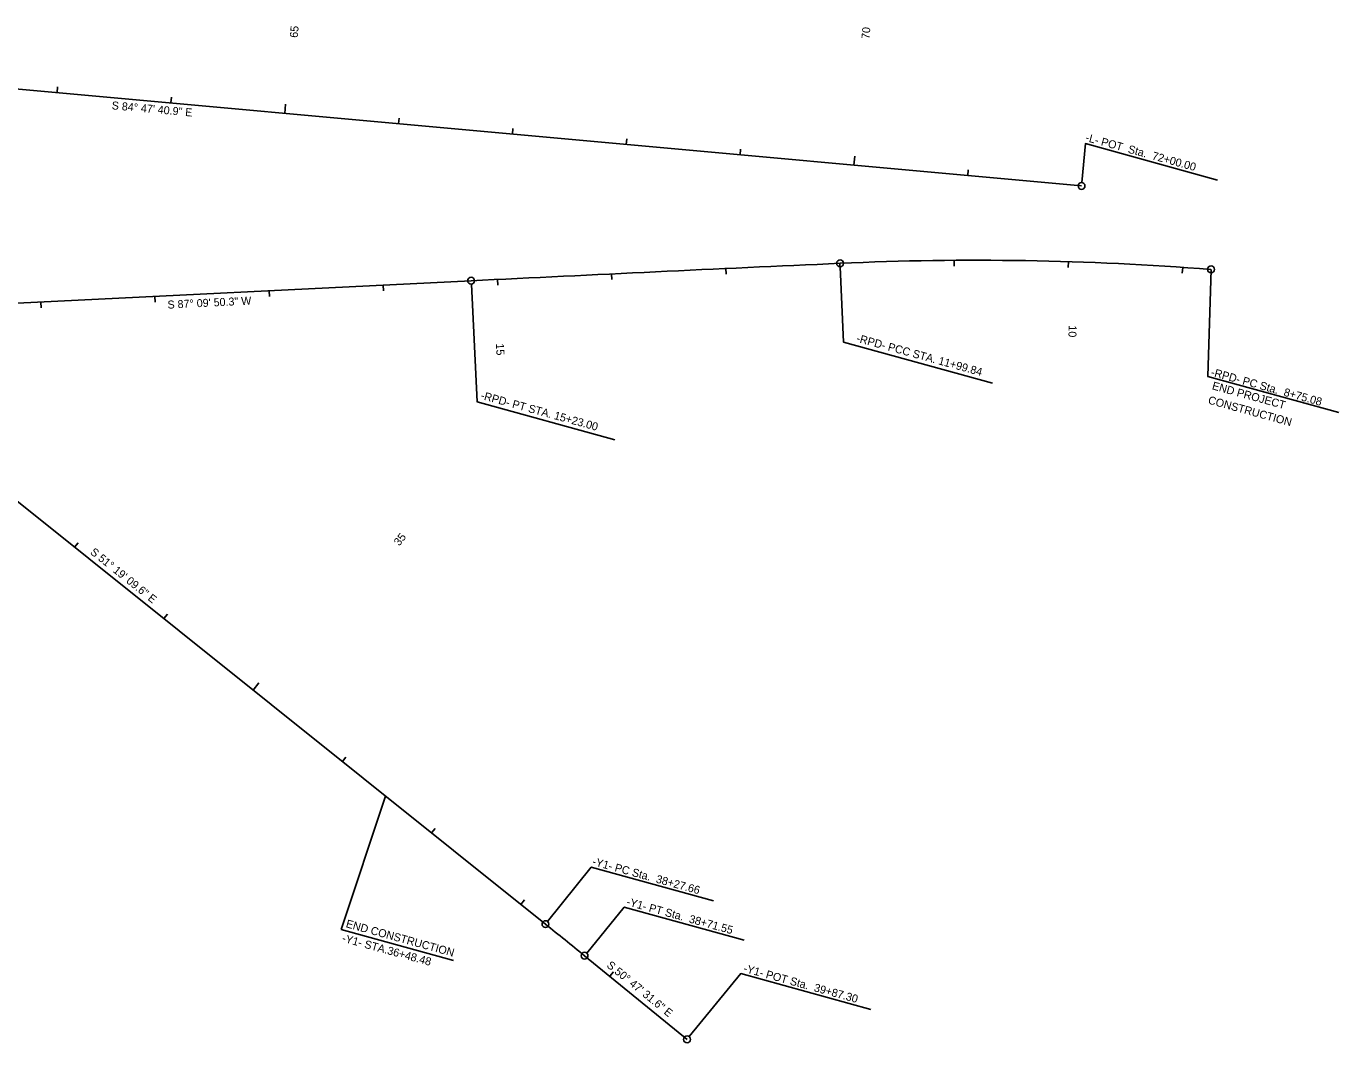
# Model space of a CAD drawing. Extents: x 1636713 to 1642889, y 841520 to 844630.
# Drawn here: x 1641741 to 1642889, y 841520 to 842410 of the extents above; entities that cross this region are included whole.
import ezdxf

# ---------------------------------------------------------------- set-up
doc = ezdxf.new("R2010")
doc.units = 0
for name, color, linetype in [('Exist 4 AWG with gnd feeder circuit in conduit', 7, 'Continuous'), ('Exist 6 AWG with gnd feeder circuit', 7, 'Continuous'), ('Exist 8 AWG with gnd feeder circuit', 7, 'Continuous'), ('Exist 8 AWG with gnd feeder circuit in conduit', 7, 'Continuous'), ('Prop 2 AWG with gnd feeder circuit in conduit', 7, 'Continuous'), ('Prop 4 AWG with gnd feeder circuit', 7, 'Continuous'), ('Prop Cable Guiderail Double Face', 7, 'Continuous')]:
    doc.layers.add(name, color=color, linetype=linetype)

msp = doc.modelspace()

# ---------------------------------------------------------------- linework, layer by layer
at = {"layer": 'Exist 6 AWG with gnd feeder circuit'}
for p, q in [((1642452.7, 842202.2), (1642453, 842197.2)), ((1642153.1, 842188.1), (1642153.3, 842183.1)), ((1642114.7, 841592.3), (1642016.3, 841619.4))]:
    msp.add_line(p, q, dxfattribs=at)
for points in [[(1642664.4, 842272.9), (1642667.5, 842306.9), (1642783.2, 842275.1)], [(1642453, 842199.2), (1642456, 842133.1)], [(1642777.4, 842196.9), (1642774.6, 842103.3), (1642889.2, 842071.7)], [(1642130.3, 842184), (1642135.4, 842081), (1642255.9, 842047.9)], [(1642456, 842133.1), (1642586.1, 842097.3)], [(1642016.3, 841619.4), (1642055.3, 841736.1)], [(1642197, 841626.4), (1642235.1, 841674), (1642342.1, 841644.6)], [(1642231.2, 841598.8), (1642264, 841639), (1642369.1, 841610.1)], [(1642320.9, 841525.7), (1642365.9, 841580.9), (1642479.8, 841549.5)]]:
    msp.add_lwpolyline(points, dxfattribs=at)
for centre in [(1642664.1, 842269.9), (1642452.9, 842202.2), (1642777.4, 842196.9), (1642130.1, 842187), (1642195.1, 841624.1), (1642229.3, 841596.5), (1642319, 841523.3)]:
    msp.add_circle(centre, 3, dxfattribs=at)
at = {"layer": 'Exist 8 AWG with gnd feeder circuit'}
for p, q in [((1641226.3, 842400.9), (1642664.1, 842269.9)), ((1642130.1, 842187), (1641529.4, 842157.2)), ((1641549.8, 842140.7), (1642195.1, 841624.1)), ((1642229.3, 841596.5), (1642319, 841523.3))]:
    msp.add_line(p, q, dxfattribs=at)
for centre, radius, start, end in [((1645629.8, 771540.6), 70733, 92.574274, 92.836038), ((1642571.8, 839556.8), 2648.1, 85.5475, 92.5743), ((1639214, 837900.4), 4770, 50.7921, 51.3193)]:
    msp.add_arc(centre, radius, start, end, dxfattribs=at)
at = {"layer": 'Prop 2 AWG with gnd feeder circuit in conduit'}
for p, q in [((1641967, 842333.4), (1641967.7, 842341.4)), ((1642465, 842288.1), (1642465.7, 842296)), ((1642652.7, 842203.7), (1642652.5, 842198.7)), ((1641939.4, 841828.9), (1641944.4, 841835.1))]:
    msp.add_line(p, q, dxfattribs=at)
at = {"layer": 'Prop 4 AWG with gnd feeder circuit'}
for p, q in [((1641767.8, 842351.6), (1641768.3, 842356.6)), ((1641867.4, 842342.5), (1641867.9, 842347.5)), ((1642066.6, 842324.4), (1642067.1, 842329.3)), ((1642166.2, 842315.3), (1642166.6, 842320.3)), ((1642265.8, 842306.2), (1642266.2, 842311.2)), ((1642365.4, 842297.1), (1642365.8, 842302.1)), ((1642564.5, 842279), (1642565, 842284)), ((1642552.7, 842204.8), (1642552.7, 842199.8)), ((1642752.6, 842198.7), (1642752.2, 842193.7)), ((1642253, 842193), (1642253.2, 842188)), ((1642352.9, 842197.7), (1642353.1, 842192.7)), ((1641953.3, 842178.2), (1641953.6, 842173.2)), ((1642053.2, 842183.2), (1642053.4, 842178.2)), ((1641753.6, 842168.3), (1641753.8, 842163.3)), ((1641853.4, 842173.3), (1641853.7, 842168.3)), ((1641783.2, 841953.9), (1641786.4, 841957.8)), ((1641861.3, 841891.4), (1641864.4, 841895.3)), ((1642017.4, 841766.4), (1642020.5, 841770.3)), ((1642095.5, 841703.9), (1642098.6, 841707.8)), ((1642173.6, 841641.4), (1642176.7, 841645.3)), ((1642251.3, 841578.5), (1642254.5, 841582.4))]:
    msp.add_line(p, q, dxfattribs=at)
at = {"layer": 'Prop Cable Guiderail Double Face'}
msp.add_line((1642130.1, 842187), (1641529.4, 842157.2), dxfattribs=at)
for centre, radius, start, end in [((1645629.8, 771540.6), 70733, 92.574274, 92.836038), ((1642571.8, 839556.8), 2648.1, 85.5475, 92.5743)]:
    msp.add_arc(centre, radius, start, end, dxfattribs=at)

# ---------------------------------------------------------------- texts
at = {"layer": 'Exist 4 AWG with gnd feeder circuit in conduit'}
for s, rotation, p in [('65', 84.7947, (1641978.3, 842399.3)), ('70', 84.7947, (1642478.5, 842398.2)), ('10', 268.2615, (1642652.9, 842148)), ('15', 272.8178, (1642151.8, 842131.9)), ('35', 51.3193, (1642067.2, 841954.5))]:
    msp.add_text(s, height=7, rotation=rotation, dxfattribs=at).set_placement(p)
at = {"layer": 'Exist 6 AWG with gnd feeder circuit'}
for s, rotation, p in [('-L- POT  Sta.  72+00.00', 344.6135, (1642667.1, 842309.3)), ('-RPD- PCC STA. 11+99.84', 344.6135, (1642466.6, 842133.7)), ('-RPD- PC Sta.  8+75.08', 344.6135, (1642776.8, 842104)), ('END PROJECT', 344.6559, (1642777.8, 842092.1)), ('-RPD- PT STA. 15+23.00', 344.6135, (1642137.9, 842083.7)), ('CONSTRUCTION', 344.6559, (1642774.3, 842079.6)), ('-Y1- PC Sta.  38+27.66', 344.6135, (1642235.6, 841675.9)), ('-Y1- PT Sta.  38+71.55', 344.6135, (1642265.5, 841640.7)), ('END CONSTRUCTION', 344.6135, (1642020, 841621.5)), ('-Y1- STA.36+48.48', 344.6135, (1642016.6, 841608.9)), ('-Y1- POT Sta.  39+87.30', 344.6135, (1642367.8, 841582.5))]:
    msp.add_text(s, height=7, rotation=rotation, dxfattribs=at).set_placement(p)
at = {"layer": 'Exist 8 AWG with gnd feeder circuit in conduit'}
for s, rotation, p in [('S 84%%d 47\' 40.9" E', 354.7947, (1641815.4, 842337)), ('S 87%%d 09\' 50.3" W', 2.836, (1641864.6, 842162.5)), ('S 51%%d 19\' 09.6" E', 321.3193, (1641796.2, 841948.5)), ('S 50%%d 47\' 31.6" E', 320.7921, (1642248.1, 841587.1))]:
    msp.add_text(s, height=7, rotation=rotation, dxfattribs=at).set_placement(p)

doc.saveas('drawing.dxf')
